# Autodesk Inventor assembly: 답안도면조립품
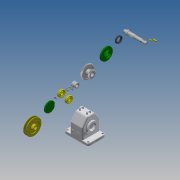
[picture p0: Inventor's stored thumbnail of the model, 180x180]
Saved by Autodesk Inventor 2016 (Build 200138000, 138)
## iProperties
Created: 2016-12
Part Number: 답안도면조립품
Document SubType Name: Assembly
Designer: Administrator
Author: Administrator
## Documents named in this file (15)
- D:\461207V1006\답안도면조립품.iam
- D:\461207V1006\본체.ipt
- D:\461207V1006\V-벨트풀리.ipt
- D:\461207V1006\뒤커버.ipt
- D:\461207V1006\멈춤나사 - M4x10.ipt
- D:\461207V1006\베어링 6203.ipt
- D:\461207V1006\볼트 M3 x 8.ipt
- D:\461207V1006\볼트 M3 x 10.ipt
- D:\461207V1006\부시.ipt
- D:\461207V1006\스퍼기어.ipt
- D:\461207V1006\앞커버.ipt
- D:\461207V1006\오일씰 28 40 8.ipt
- D:\461207V1006\축.ipt
- D:\461207V1006\키 - 5 x 5 x 18.ipt
- D:\461207V1006\키 - 6 x 6 x 22.ipt
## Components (9 placed, 3 different names)
1. V-벨트풀리:1
2. ISO 4762 M3 x 8:1
3. ISO 4762 M3 x 10:1
4. ISO 4762 M3 x 8:2
5. ISO 4762 M3 x 8:3
6. ISO 4762 M3 x 8:4
7. ISO 4762 M3 x 10:2
8. ISO 4762 M3 x 10:3
9. ISO 4762 M3 x 10:4
